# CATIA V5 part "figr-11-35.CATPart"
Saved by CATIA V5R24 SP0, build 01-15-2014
Part number: Part1
Bounding box of the stored display mesh (mm): x -55 to 66, y 20 to 170, z -50 to 0
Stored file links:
  D:\KAVITA\CATIA V5-6R2014 Project_ Kavita\CATIA V5-6R2014_partfiles\Partfiles\c11_catia_v5-6r2014_prt\figr-11-35.CATPart
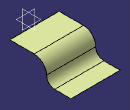
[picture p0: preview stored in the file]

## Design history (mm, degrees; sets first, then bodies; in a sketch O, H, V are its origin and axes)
Set1
  Extrude1: Element1 Sketch1, Lim1 66, Lim2 55, Direction yz-plane
  Symmetry1: ToTransfor Extrude1, Reference zx-plane
Body1 (main body)
  Sketch1 on yz-plane, origin (0, 0, 0), H (0, 1, 0), V (0, 0, 1)
    point P1 (20, 0)
    line L1 (20, 0) -> (80, 0)
    arc A1 centre (80, -30) radius 30 from (80, 0) to (110, -30) cw
    arc A2 centre (130, -30) radius 20 from (110, -30) to (130, -50) ccw
    line L2 (130, -50) -> (170, -50)
    coincidence: P1 H
    horizontal: L1 H
    tangency: A1 L1, A2 A1, L2 A2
